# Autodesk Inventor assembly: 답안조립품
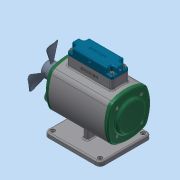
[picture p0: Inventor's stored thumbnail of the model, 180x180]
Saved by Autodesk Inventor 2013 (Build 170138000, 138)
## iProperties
Created: 2016-06
Part Number: 답안조립품
Document SubType Name: Assembly
Designer: Administrator
Author: Administrator
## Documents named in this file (19)
- C:\Users\Administrator\Desktop\360608V1015\답안조립품.iam
- C:\Users\Administrator\Desktop\360608V1015\15 스프링.ipt
- C:\Users\Administrator\Desktop\360608V1015\16 스프링.ipt
- C:\Users\Administrator\Desktop\360608V1015\17 스프링.ipt
- C:\Users\Administrator\Desktop\360608V1015\뒷커버.ipt
- C:\Users\Administrator\Desktop\360608V1015\멈춤나사 M4x5.ipt
- C:\Users\Administrator\Desktop\360608V1015\베어링 6203.ipt
- C:\Users\Administrator\Desktop\360608V1015\본체.ipt
- C:\Users\Administrator\Desktop\360608V1015\볼트 M4 x 12.ipt
- C:\Users\Administrator\Desktop\360608V1015\볼트 M4 x 16.ipt
- C:\Users\Administrator\Desktop\360608V1015\부시.ipt
- C:\Users\Administrator\Desktop\360608V1015\슬라이드.ipt
- C:\Users\Administrator\Desktop\360608V1015\앞커버.ipt
- C:\Users\Administrator\Desktop\360608V1015\오일실 17 30 8.ipt
- C:\Users\Administrator\Desktop\360608V1015\축.ipt
- C:\Users\Administrator\Desktop\360608V1015\키 - 5 x 5 x 18.ipt
- C:\Users\Administrator\Desktop\360608V1015\팬날개.ipt
- 팬날개.ipt
- C:\Users\Administrator\Desktop\360608V1015\헤더커버.ipt
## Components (6 placed, 5 different names)
1. 15 스프링:1
2. 16 스프링:1
3. 17 스프링:1
4. 7-베어링 6203:1
5. 헤더커버:1
6. 7-베어링 6203:2
